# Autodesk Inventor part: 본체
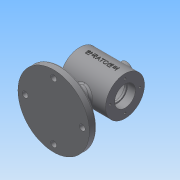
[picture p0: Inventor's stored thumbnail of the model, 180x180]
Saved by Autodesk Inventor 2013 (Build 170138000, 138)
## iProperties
Created: 2018-12
Part Number: 본체
Material: 일반
Document SubType Name: Modeling
Designer: Administrator
Density: 1 g/cm^3
Author: Administrator
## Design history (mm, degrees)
sketch "스케치1"
  geometry: C1 r 30 at (0, 0); 1 further point
  constraints: 1 centre point, 1 coincident
  dimensions: "d0" = 60 diameter of C1
extrude "돌출1" new body sketch "스케치1" distance "d1" = 70; taper "d2" = 0 deg
sketch "스케치2"
  geometry: L1 (0, 30)-(70, 30) reference; L2 (70, 30)-(70, -30) reference; L3 (70, -30)-(0, -30) reference; L4 (0, -30)-(0, 30) reference; L5 (0, 16)-(12, 16); L6 (12, 16)-(12, 14); L7 (12, 14)-(15, 14); L8 (15, 14)-(15, 25); L9 (15, 25)-(55, 25); L10 (55, 25)-(55, 14); L11 (55, 14)-(58, 14); L12 (58, 14)-(58, 16); L13 (58, 16)-(70, 16); L14 (0, 0)-(70, 0); L15 (0, 30)-(70, 30) reference; L16 (70, 30)-(70, -30) reference; L17 (70, -30)-(0, -30) reference; L18 (0, -30)-(0, 30) reference
  constraints: 20 end point, 6 parallel, 3 perpendicular, 2 collinear, 2 point on line, 1 midpoint
  dimensions: "d3" = 32 diameter of L13 L14; "d5" = 12 distance of L12.end L13.end; "d6" = 12 distance of L5.start L5.end; "d7" = 28 diameter of L11 L14; "d8" = 3 distance of L10.end L11.end; "d9" = 3 distance of L6.end L7.end; "d10" = 50 diameter of L9 L14; "d11" = 40 distance of L8.end L9.end (derived)
revolve "회전1" sketch "스케치2" stored, may be unused: angle "d12" = 90 deg
sketch "스케치3"
  geometry: C1 r 16 at (0, 0) reference; 2 further points
  constraints: 1 vertical alignment
  dimensions: "d13" = 23 distance of point (0, 23) point (0, 0)
hole "구멍1" sketch "스케치3" at (0, 23) diameter "d14" = 3.242; stored, may be unused: countersink angle "d18" = 90 deg, drill point angle "d20" = 118 deg; dims "d15" = 8, "d16" = 4, "d17" = 2, "d19" = 10
node "작업 평면1"
node "작업 평면2"
node "작업 평면3"
sketch "스케치8"
  geometry: L1 (0, -30)-(0, 30) reference; C1 r 55 at (-35, 0); 1 further point
  constraints: 1 centre point, 1 horizontal alignment
  dimensions: "d31" = 110 diameter of C1; "d32" = 35 distance from line of C1.centre L1
extrude "돌출3" join sketch "스케치8" distance "d33" = 11; taper "d34" = 0 deg
sketch "스케치10"
  geometry: C1 r 55 at (0, 0) reference; 1 further point
extrude "돌출4" join sketch "스케치10" distance "d35" = 15; taper "d36" = -75 deg
sketch "스케치11"
  geometry: C1 r 55 at (0, 0) reference; C2 r 12 at (0, 0); 2 further points
  constraints: 1 centre point, 1 coincident
  dimensions: "d37" = 24 diameter of C2
extrude "돌출5" join sketch "스케치11" stored distance "d38" = 15; taper "d39" = 0 deg
fillet "모깎기2" dims "d40" = 3
node "작업 평면4"
sketch "스케치15"
  geometry: L1 (-35, 30)-(-35, -30) reference; C1 r 10 at (0, 0); 1 further point
  constraints: 1 centre point, 1 horizontal alignment
  dimensions: "d44" = 20 diameter of C1; "d45" = 35 distance from line of C1.centre L1
extrude "돌출6" join sketch "스케치15" stored distance "d46" = 15; taper "d47" = 0 deg
sketch "스케치16"
  geometry: C1 r 10 at (0, 0) reference; C2 r 5 at (0, 0); 1 further point
  constraints: 1 centre point, 1 coincident
  dimensions: "d48" = 10 diameter of C2
extrude "돌출7" cut sketch "스케치16" stored distance "d49" = 15; taper "d50" = 0 deg
sketch "스케치17"
  geometry: C1 r 55 at (0, 0) reference; 2 further points
  constraints: 1 vertical alignment
  dimensions: "d51" = 44 distance of point (0, -44) C1.centre
hole "구멍2" sketch "스케치17" at (0, -44) diameter "d52" = 9; stored, may be unused: countersink angle "d56" = 90 deg, drill point angle "d58" = 118 deg; dims "d53" = 8, "d54" = 14, "d55" = 2, "d57" = 10
node "작업 평면5"
sketch "스케치18"
  geometry: C1 r 4.5 at (0, -44) reference; C2 r 55 at (0, 0) reference; 2 further points
  constraints: 1 coincident
hole "구멍3" sketch "스케치18" at (0, -44) diameter "d60" = 14; stored, may be unused: countersink angle "d64" = 90 deg, drill point angle "d66" = 118 deg; dims "d61" = 8, "d62" = 14, "d63" = 2, "d65" = 10
node "작업 평면6"
sketch "스케치19"
  geometry: L1 (0, 30)-(0, -30) reference; L2 (0, 30)-(70, 30) reference; 2 further points
  constraints: 1 other
  dimensions: "d71" = 35 distance from line of point (35, 0) L1; "d72" = 30 distance from line of point (35, 0) L2
feature "엠보싱1" sketch "스케치19" dims "d1" = 70, "d2" = 0, "d73" = 0.5, "d74" = 0
node "솔리드1"
pattern_circular "원형 패턴1" dims angle "d22" = 360 deg
mirror "대칭1"
pattern_circular "원형 패턴2" dims angle "d68" = 360 deg
node "투영된 루프1"
node "투영된 루프2"
node "투영된 루프5"
node "투영된 루프6"
node "투영된 루프7"
node "절단 모서리 투영1"
node "절단 모서리 투영2"
other parameters: "d24" = -75, "d30" = -75, "d43" = -112, "d70" = 80.5
